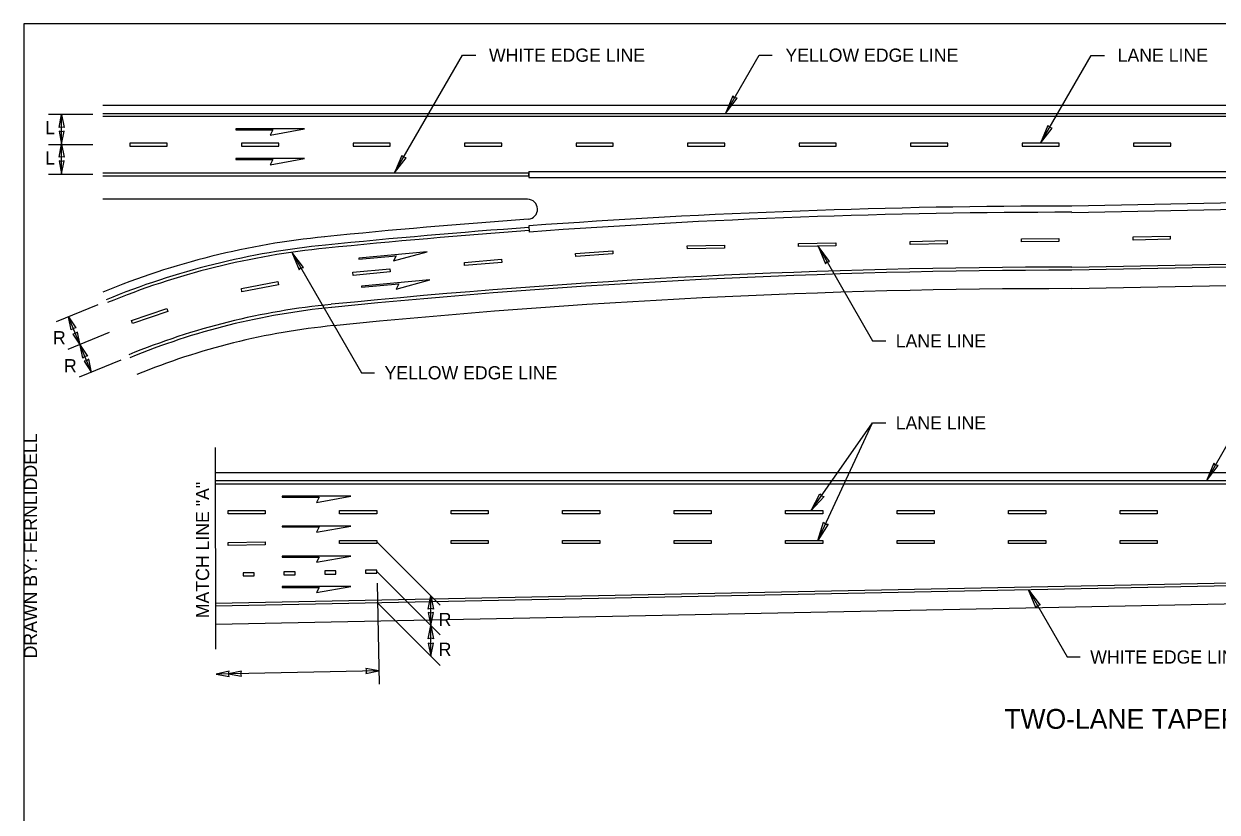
# Model space of a CAD drawing. Extents: x 99862 to 103151, y 100339 to 102415.
# Drawn here: x 99862 to 101307, y 101461 to 102415 of the extents above; entities that cross this region are included whole.
import ezdxf

# ---------------------------------------------------------------- set-up
doc = ezdxf.new("R2010")
doc.units = 0
for name, color, linetype in [('Level 1', 7, 'Continuous'), ('Level 15', 7, 'Continuous'), ('Level 2', 7, 'Continuous'), ('Level 20', 7, 'Continuous'), ('Level 3', 7, 'Continuous'), ('Level 4', 7, 'Continuous'), ('Level 5', 7, 'Continuous'), ('Level 6', 7, 'Continuous'), ('Level 62', 7, 'Continuous')]:
    doc.layers.add(name, color=color, linetype=linetype)

msp = doc.modelspace()

# ---------------------------------------------------------------- linework, layer by layer
at = {"layer": 'Level 1'}
msp.add_lwpolyline([(99862, 100338.8), (103151, 100338.8), (103151, 102414.8), (99862, 102414.8)], close=True, dxfattribs=at)
at = {"layer": 'Level 15'}
for p, q in [((100310.8, 102234.4), (100393.1, 102376.9)), ((100393.1, 102376.9), (100409.1, 102376.9)), ((100711.4, 102306.4), (100752.1, 102376.9)), ((100752.1, 102376.9), (100768.1, 102376.9)), ((101093, 102270.4), (101154.3, 102376.5)), ((101154.3, 102376.5), (101170.3, 102376.5)), ((99945.7, 102305), (99891.7, 102305)), ((99907.7, 102269.1), (99907.7, 102305)), ((99945.7, 102268.5), (99891.7, 102268.5)), ((99907.7, 102233.2), (99907.7, 102269.1)), ((99945.7, 102232.5), (99891.7, 102232.5)), ((100823.5, 102145.6), (100889.6, 102031.2)), ((100186.6, 102138.4), (100270.7, 101992.6)), ((99951.5, 102074.9), (99901.3, 102054.1)), ((99930.2, 102026), (99916.1, 102060.2)), ((99965.4, 102041.4), (99915.2, 102020.6)), ((100889.6, 102031.2), (100905.6, 102031.2)), ((99943.9, 101993.1), (99930.2, 102026)), ((99979.3, 102008), (99929, 101987.2)), ((100270.7, 101992.6), (100286.7, 101992.6)), ((100815.3, 101825.8), (100889.6, 101932)), ((100823.3, 101789.8), (100889.6, 101932)), ((100889.6, 101932), (100905.6, 101932)), ((101293.8, 101861.8), (101334.3, 101932)), ((100365.9, 101711.4), (100289.3, 101788)), ((100365.9, 101675.4), (100289.3, 101752)), ((100289.6, 101738.1), (100292.1, 101616)), ((101078.3, 101729.9), (101125.1, 101648.7)), ((100366, 101638.3), (100289.3, 101715)), ((100354.7, 101686.6), (100354.7, 101722.6)), ((100354.7, 101649.6), (100354.7, 101686.6)), ((101125.1, 101648.7), (101141.1, 101648.7))]:
    msp.add_line(p, q, dxfattribs=at)
for points in [[(100711.4, 102306.4), (100725.5, 102324.7), (100722.3, 102325.3), (100720.3, 102327.7)], [(99907.7, 102305), (99910.8, 102289.2), (99907.7, 102289.9), (99904.6, 102289.2)], [(101093, 102270.4), (101107.1, 102288.7), (101104, 102289.3), (101101.9, 102291.7)], [(99907.7, 102269.1), (99910.8, 102284.9), (99907.7, 102284.2), (99904.6, 102284.9)], [(99907.7, 102269.1), (99910.8, 102253.3), (99907.7, 102254), (99904.6, 102253.3)], [(99907.7, 102233.2), (99910.8, 102249), (99907.7, 102248.3), (99904.6, 102249)], [(100310.8, 102234.4), (100324.9, 102252.7), (100321.8, 102253.3), (100319.7, 102255.7)], [(100823.5, 102145.6), (100832.4, 102124.4), (100834.4, 102126.8), (100837.5, 102127.4)], [(100186.6, 102138.4), (100195.4, 102117.1), (100197.4, 102119.6), (100200.6, 102120.1)], [(99916.1, 102060.2), (99925, 102046.8), (99921.9, 102046.3), (99919.3, 102044.4)], [(99930.2, 102026), (99927.1, 102041.8), (99924.5, 102040), (99921.3, 102039.5)], [(99930.2, 102026), (99939.1, 102012.6), (99936, 102012.1), (99933.4, 102010.3)], [(99943.9, 101993.1), (99940.7, 102008.9), (99938.1, 102007), (99935, 102006.5)], [(101293.8, 101861.8), (101307.9, 101880.2), (101304.8, 101880.8), (101302.7, 101883.2)], [(100815.3, 101825.8), (100825.9, 101846.3), (100827.8, 101843.7), (100830.8, 101842.8)], [(100823.3, 101789.8), (100830.3, 101811.8), (100832.5, 101809.6), (100835.7, 101809.3)], [(101078.3, 101729.9), (101092.3, 101711.5), (101089.2, 101710.9), (101087.1, 101708.5)], [(100354.7, 101722.6), (100357.8, 101706.7), (100354.7, 101707.5), (100351.6, 101706.7)], [(100354.7, 101686.6), (100357.8, 101702.4), (100354.7, 101701.7), (100351.6, 101702.4)], [(100354.7, 101686.6), (100357.8, 101670.8), (100354.7, 101671.5), (100351.6, 101670.8)], [(100354.7, 101649.6), (100357.8, 101665.4), (100354.7, 101664.7), (100351.6, 101665.4)], [(100094.7, 101628), (100110.5, 101625.2), (100109.7, 101628.3), (100110.4, 101631.4)], [(100109.7, 101628.3), (100125.6, 101625.5), (100124.8, 101628.6), (100125.5, 101631.7)], [(100291.7, 101632), (100275.9, 101634.8), (100276.7, 101631.7), (100276, 101628.6)]]:
    msp.add_lwpolyline(points, close=True, dxfattribs=at)
msp.add_lwpolyline([(100291.7, 101632), (100094.7, 101628)], dxfattribs=at)
at = {"layer": 'Level 2'}
for p, q in [((99957.8, 102316.5), (103035.2, 102316.5)), ((100471.9, 102202.5), (99957.8, 102202.5)), ((101130.9, 102094.5), (103035.2, 102132.6)), ((100094.2, 101872), (102179.3, 101872))]:
    msp.add_line(p, q, dxfattribs=at)
msp.add_lwpolyline([(102179.3, 101720.1), (101695.8, 101720.1), (100094.2, 101688)], dxfattribs=at)
for centre, radius, start, end in [((100471.9, 102190.5), 12, 274.1713, 90), ((101130.9, 93154.5), 9048, 94.17133, 95.73917), ((100318.5, 101213.6), 948, 95.5849, 112.3657), ((101130.9, 93154.3), 8940.1, 90.00002, 95.74014), ((100318.5, 101213.6), 840, 95.5849, 112.3657)]:
    msp.add_arc(centre, radius, start, end, dxfattribs=at)
at = {"layer": 'Level 3'}
for p, q in [((99957.8, 102306.4), (103035.2, 102306.4)), ((103035.2, 102302.6), (99957.8, 102302.6)), ((100473.5, 102236.2), (100473.5, 102228.7)), ((100473.5, 102236.2), (102330.7, 102236.2)), ((100473.5, 102228.7), (102330.7, 102228.7)), ((100473.4, 102170.3), (100473.9, 102162.8)), ((101130.9, 102120.4), (103035.2, 102158.4)), ((103035.2, 102154.7), (101130.9, 102116.6)), ((102179.3, 101861.8), (100094.2, 101861.8)), ((100094.2, 101858.1), (102179.3, 101858.1))]:
    msp.add_line(p, q, dxfattribs=at)
for points in [[(99957.8, 102234.4), (100473.5, 102234.4)], [(100473.5, 102230.6), (99957.8, 102230.6)], [(101131, 102186.7), (102330.8, 102210.7), (102330.7, 102218.2), (101130.8, 102194.2)], [(100094.2, 101713.9), (102089.3, 101753.8), (102179.3, 101753.8)], [(102179.3, 101750.1), (102089.3, 101750.1), (100094.2, 101710.2)]]:
    msp.add_lwpolyline(points, dxfattribs=at)
for centre, radius, start, end in [((101130.9, 93154.5), 9039.8, 90, 94.17133), ((101130.9, 93154.5), 9032.3, 90, 94.17133), ((101130.9, 93154.5), 9037.9, 94.17133, 95.73917), ((101130.9, 93154.5), 9034.1, 94.17133, 95.73917), ((100318.5, 101213.6), 937.9, 95.5849, 112.3657), ((100318.5, 101213.6), 934.1, 95.5849, 112.3657), ((101130.9, 93154.4), 8966, 90.00002, 95.73971), ((101130.9, 93154.5), 8962.1, 90, 95.73917), ((100318.5, 101213.6), 865.9, 95.5849, 112.3657), ((100318.5, 101213.6), 862.1, 95.5849, 112.3657)]:
    msp.add_arc(centre, radius, start, end, dxfattribs=at)
at = {"layer": 'Level 4'}
for points in [[(100035.5, 102270.4), (99990.5, 102270.4), (99990.5, 102266.6), (100035.5, 102266.6)], [(100170.5, 102270.4), (100125.5, 102270.4), (100125.5, 102266.6), (100170.5, 102266.6)], [(100305.5, 102270.4), (100260.5, 102270.4), (100260.5, 102266.6), (100305.5, 102266.6)], [(100440.5, 102270.4), (100395.5, 102270.4), (100395.5, 102266.6), (100440.5, 102266.6)], [(100575.5, 102270.4), (100530.5, 102270.4), (100530.5, 102266.6), (100575.5, 102266.6)], [(100710.5, 102270.4), (100665.5, 102270.4), (100665.5, 102266.6), (100710.5, 102266.6)], [(100845.5, 102270.4), (100800.5, 102270.4), (100800.5, 102266.6), (100845.5, 102266.6)], [(100980.5, 102270.4), (100935.5, 102270.4), (100935.5, 102266.6), (100980.5, 102266.6)], [(101115.5, 102270.4), (101070.5, 102270.4), (101070.5, 102266.6), (101115.5, 102266.6)], [(101250.5, 102270.4), (101205.5, 102270.4), (101205.5, 102266.6), (101250.5, 102266.6)], [(100665.2, 102146.2), (100710.2, 102147.1), (100710.3, 102143.4), (100665.3, 102142.4)], [(100799.9, 102149), (100844.9, 102149.8), (100845, 102146), (100800, 102145.2)], [(100934.9, 102151.5), (100979.9, 102152.5), (100980, 102148.7), (100935, 102147.8)], [(101070, 102154.7), (101114.9, 102155.2), (101115, 102151.4), (101070, 102150.9)], [(101204.9, 102157), (101249.9, 102157.9), (101250, 102154.1), (101205, 102153.2)], [(100395.3, 102126.2), (100440.1, 102130), (100440.5, 102126.2), (100395.6, 102122.4)], [(100530, 102137.1), (100574.9, 102140.2), (100575.2, 102136.5), (100530.3, 102133.4)], [(100260.3, 102114.2), (100305.1, 102118.3), (100305.5, 102114.6), (100260.7, 102110.5)], [(100125.3, 102094.4), (100169.5, 102102.9), (100170.2, 102099.2), (100126.1, 102090.7)], [(99992.3, 102055.9), (100035, 102070.4), (100036.2, 102066.8), (99993.6, 102052.4)], [(100109.3, 101825.8), (100154.3, 101825.8), (100154.3, 101822.1), (100109.3, 101822.1)], [(100244.3, 101825.8), (100289.3, 101825.8), (100289.3, 101822.1), (100244.3, 101822.1)], [(100379.3, 101825.8), (100424.3, 101825.8), (100424.3, 101822.1), (100379.3, 101822.1)], [(100514.3, 101825.8), (100559.3, 101825.8), (100559.3, 101822.1), (100514.3, 101822.1)], [(100649.3, 101825.8), (100694.3, 101825.8), (100694.3, 101822.1), (100649.3, 101822.1)], [(100784.3, 101825.8), (100829.3, 101825.8), (100829.3, 101822.1), (100784.3, 101822.1)], [(100919.3, 101825.8), (100964.3, 101825.8), (100964.3, 101822.1), (100919.3, 101822.1)], [(101054.3, 101825.8), (101099.3, 101825.8), (101099.3, 101822.1), (101054.3, 101822.1)], [(101189.3, 101825.8), (101234.3, 101825.8), (101234.3, 101822.1), (101189.3, 101822.1)], [(100109.3, 101787.1), (100154.3, 101788), (100154.3, 101784.3), (100109.3, 101783.4)], [(100244.3, 101789.8), (100289.3, 101789.8), (100289.3, 101786.1), (100244.3, 101786.1)], [(100379.3, 101789.8), (100424.3, 101789.8), (100424.3, 101786.1), (100379.3, 101786.1)], [(100514.3, 101789.8), (100559.3, 101789.8), (100559.3, 101786.1), (100514.3, 101786.1)], [(100649.3, 101789.8), (100694.3, 101789.8), (100694.3, 101786.1), (100649.3, 101786.1)], [(100784.3, 101789.8), (100829.3, 101789.8), (100829.3, 101786.1), (100784.3, 101786.1)], [(100919.3, 101789.8), (100964.3, 101789.8), (100964.3, 101786.1), (100919.3, 101786.1)], [(101054.3, 101789.8), (101099.3, 101789.8), (101099.3, 101786.1), (101054.3, 101786.1)], [(101189.3, 101789.8), (101234.3, 101789.8), (101234.3, 101786.1), (101189.3, 101786.1)], [(100275.8, 101750.1), (100289.3, 101750.1), (100289.3, 101753.8), (100275.8, 101753.8)], [(100127.4, 101746.9), (100140.9, 101746.9), (100140.9, 101750.7), (100127.4, 101750.7)], [(100176.9, 101748), (100190.4, 101748), (100190.4, 101751.7), (100176.9, 101751.7)], [(100226.4, 101749), (100239.9, 101749), (100239.9, 101752.8), (100226.4, 101752.8)]]:
    msp.add_lwpolyline(points, close=True, dxfattribs=at)
at = {"layer": 'Level 5'}
msp.add_line((100473.5, 102230.6), (100473.5, 102234.4), dxfattribs=at)
for points in [[(100118.6, 102286.5), (100163.6, 102286.5), (100160.1, 102280.3), (100201.6, 102287.7), (100118.6, 102287.7)], [(100118.6, 102250.5), (100163.6, 102250.5), (100160.1, 102244.3), (100201.6, 102251.7), (100118.6, 102251.7)], [(100267.7, 102130.1), (100312.6, 102134.3), (100309.6, 102127.9), (100350.3, 102139.1), (100267.6, 102131.3)], [(100270.9, 102096.1), (100315.8, 102100.4), (100312.8, 102093.9), (100353.5, 102105.1), (100270.8, 102097.3)], [(100174.7, 101842), (100219.7, 101842), (100216.2, 101835.8), (100257.7, 101843.1), (100174.7, 101843.1)], [(100174.7, 101806), (100219.7, 101806), (100216.2, 101799.8), (100257.7, 101807.1), (100174.7, 101807.1)], [(100174.7, 101769.5), (100219.7, 101769.5), (100216.2, 101763.4), (100257.7, 101770.7), (100174.7, 101770.7)], [(100174.7, 101732.8), (100219.7, 101732.8), (100216.2, 101726.7), (100257.7, 101734), (100174.7, 101734)]]:
    msp.add_lwpolyline(points, close=True, dxfattribs=at)
at = {"layer": 'Level 6'}
msp.add_line((100094.3, 101658), (100094.2, 101902), dxfattribs=at)

# ---------------------------------------------------------------- texts
at = {"layer": 'Level 20'}
for s, height, p in [('WHITE EDGE LINE', 16, (100425.1, 102368.9)), ('YELLOW EDGE LINE', 16, (100784.1, 102368.9)), ('LANE LINE', 16, (101186.3, 102368.9)), ('L', 16, (99887.8, 102281.2)), ('L', 16, (99887.8, 102244.6)), ('R', 16, (99897.2, 102027)), ('LANE LINE', 16, (100917.6, 102023.2)), ('R', 16, (99910.6, 101993.1)), ('YELLOW EDGE LINE', 16, (100298.7, 101984.6)), ('LANE LINE', 16, (100917.6, 101924)), ('R', 16, (100364.2, 101686)), ('R', 16, (100364.2, 101650)), ('WHITE EDGE LINE', 16, (101153.1, 101640.7)), ('TWO-LANE TAPERED ON-CONNECTION', 24, (101049.1, 101561.8))]:
    msp.add_text(s, height=height, dxfattribs=at).set_placement(p)
msp.add_text('MATCH LINE "A"', height=16, rotation=90, dxfattribs=at).set_placement((100086.3, 101695.6))
at = {"layer": 'Level 62'}
msp.add_text('DRAWN BY: FERNLIDDELL', height=16, rotation=90, dxfattribs=at).set_placement((99878, 101647))

doc.saveas('drawing.dxf')
